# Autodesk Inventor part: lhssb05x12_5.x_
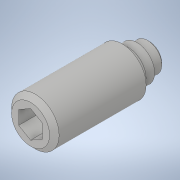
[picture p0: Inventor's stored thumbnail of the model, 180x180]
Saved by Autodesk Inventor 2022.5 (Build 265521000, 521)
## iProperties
Created: 2021-02
Part Number: lhssb05x12_5.x_
Material: 一般
Document SubType Name: Modeling
Designer: ImaoCorp
Density: 1 g/cm^3
Appearance: 既定
Sending System: SOLIDWORKS 2019-2019304
MC: AMD64
MC_MODEL: Intel64 Family 6 Model 60 Stepping 3, GenuineIntel
OS: Windows_NT
FRU: Parasolid Version 31.0, build 290,  9- 1-2019
FORMAT: text
GUISE: transmit
KEY: lhssb05x12_5
FILE: lhssb05x12_5.x_t
DATE: Mon Feb 22 14:56:20 2021
Author: ImaoCorp
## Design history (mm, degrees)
feature "Base1"
node "ソリッド1"
